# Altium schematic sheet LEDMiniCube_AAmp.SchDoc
size A4
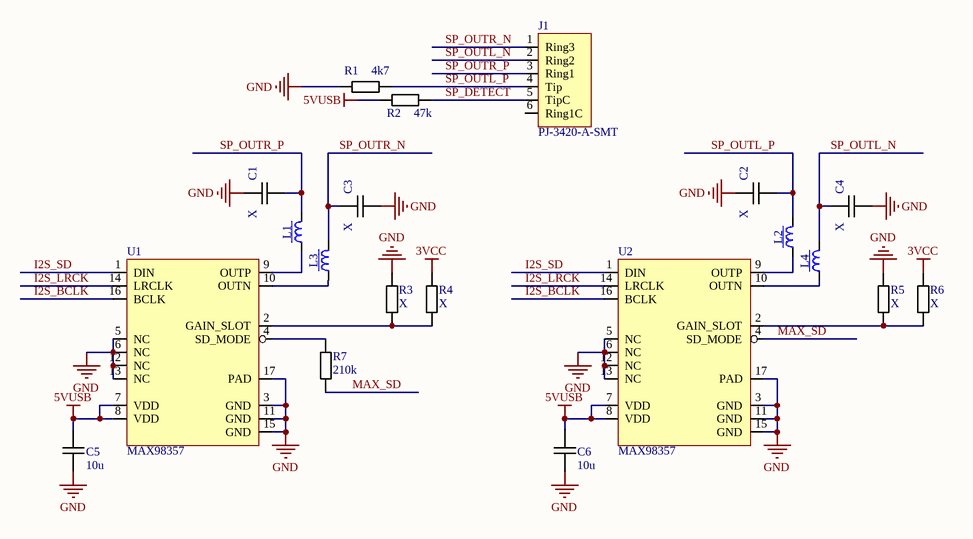
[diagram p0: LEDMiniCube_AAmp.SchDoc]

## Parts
C1  X  [CAPC2012L]
C2  X  [CAPC2012L]
C3  X  [CAPC2012L]
C4  X  [CAPC2012L]
C5  10u  [CAPC2012L]
C6  10u  [CAPC2012L]
J1  PJ-3420-A-SMT  [PJ-3420-A-SMT]
L1  (no value)  [INDC2012L]
L2  (no value)  [INDC2012L]
L3  (no value)  [INDC2012L]
L4  (no value)  [INDC2012L]
R1  4k7  [RESC1608L]
R2  47k  [RESC1608L]
R3  X  [RESC1608L]
R4  X  [RESC1608L]
R5  X  [RESC1608L]
R6  X  [RESC1608L]
R7  210k  [RESC1608L]
U1  MAX98357  [PQFN50P300X300X80_HS-17N]
U2  MAX98357  [PQFN50P300X300X80_HS-17N]

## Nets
3VCC: R4.2 R6.2
5VUSB: C5.2 C6.2 R2.1 U1.7(VDD) U1.8(VDD) U2.7(VDD) U2.8(VDD)
GND: C1.1 C2.1 C3.2 C4.2 C5.1 C6.1 R1.1 R3.2 R5.2 U1.3(GND) U1.5(NC) U1.6(NC) U1.11(GND) U1.12(NC) U1.13(NC) U1.15(GND) U1.17(PAD) U2.3(GND) U2.5(NC) U2.6(NC) U2.11(GND) U2.12(NC) U2.13(NC) U2.15(GND) U2.17(PAD)
I2S_BCLK: U1.16(BCLK) U2.16(BCLK)
I2S_LRCK: U1.14(LRCLK) U2.14(LRCLK)
I2S_SD: U1.1(DIN) U2.1(DIN)
MAX_SD: R7.2 U2.4(SD_MODE)
SP_DETECT: J1.5(TipC) R2.2
SP_OUTL_N: C4.1 J1.2(Ring2) L4.2
SP_OUTL_P: C2.2 J1.4(Tip) L2.2 R1.2
SP_OUTR_N: C3.1 J1.1(Ring3) L3.2
SP_OUTR_P: C1.2 J1.3(Ring1) L1.2
NetL1_1: L1.1 U1.9(OUTP)
NetL2_1: L2.1 U2.9(OUTP)
NetL3_1: L3.1 U1.10(OUTN)
NetL4_1: L4.1 U2.10(OUTN)
NetR3_1: R3.1 R4.1 U1.2(GAIN_SLOT)
NetR5_1: R5.1 R6.1 U2.2(GAIN_SLOT)
NetR7_1: R7.1 U1.4(SD_MODE)

Not connected (* = marked no-connect by the designer): J1 6(Ring1C)

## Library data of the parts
C1-C6 = Capacitor
J1 = 3.5 socket PJ-3420-A-SMT
L1-L4 = IND_150NH_2%_COILCRAFT_0805CS: Inductor With Core
R1-R7 = Resistor
U1 U2 = MAX98357: Part: MAX98357A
